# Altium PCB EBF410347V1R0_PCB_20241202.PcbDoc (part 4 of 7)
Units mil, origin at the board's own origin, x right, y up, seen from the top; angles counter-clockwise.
Board outline 5098.43 x 3464.57 mil, 6 copper layers (TOP, GND02, ART03, ART04, PWR05, BOTTOM), stack 47.2 mil thick; 566 components, 452 nets, 1905 pads, 1432 vias.
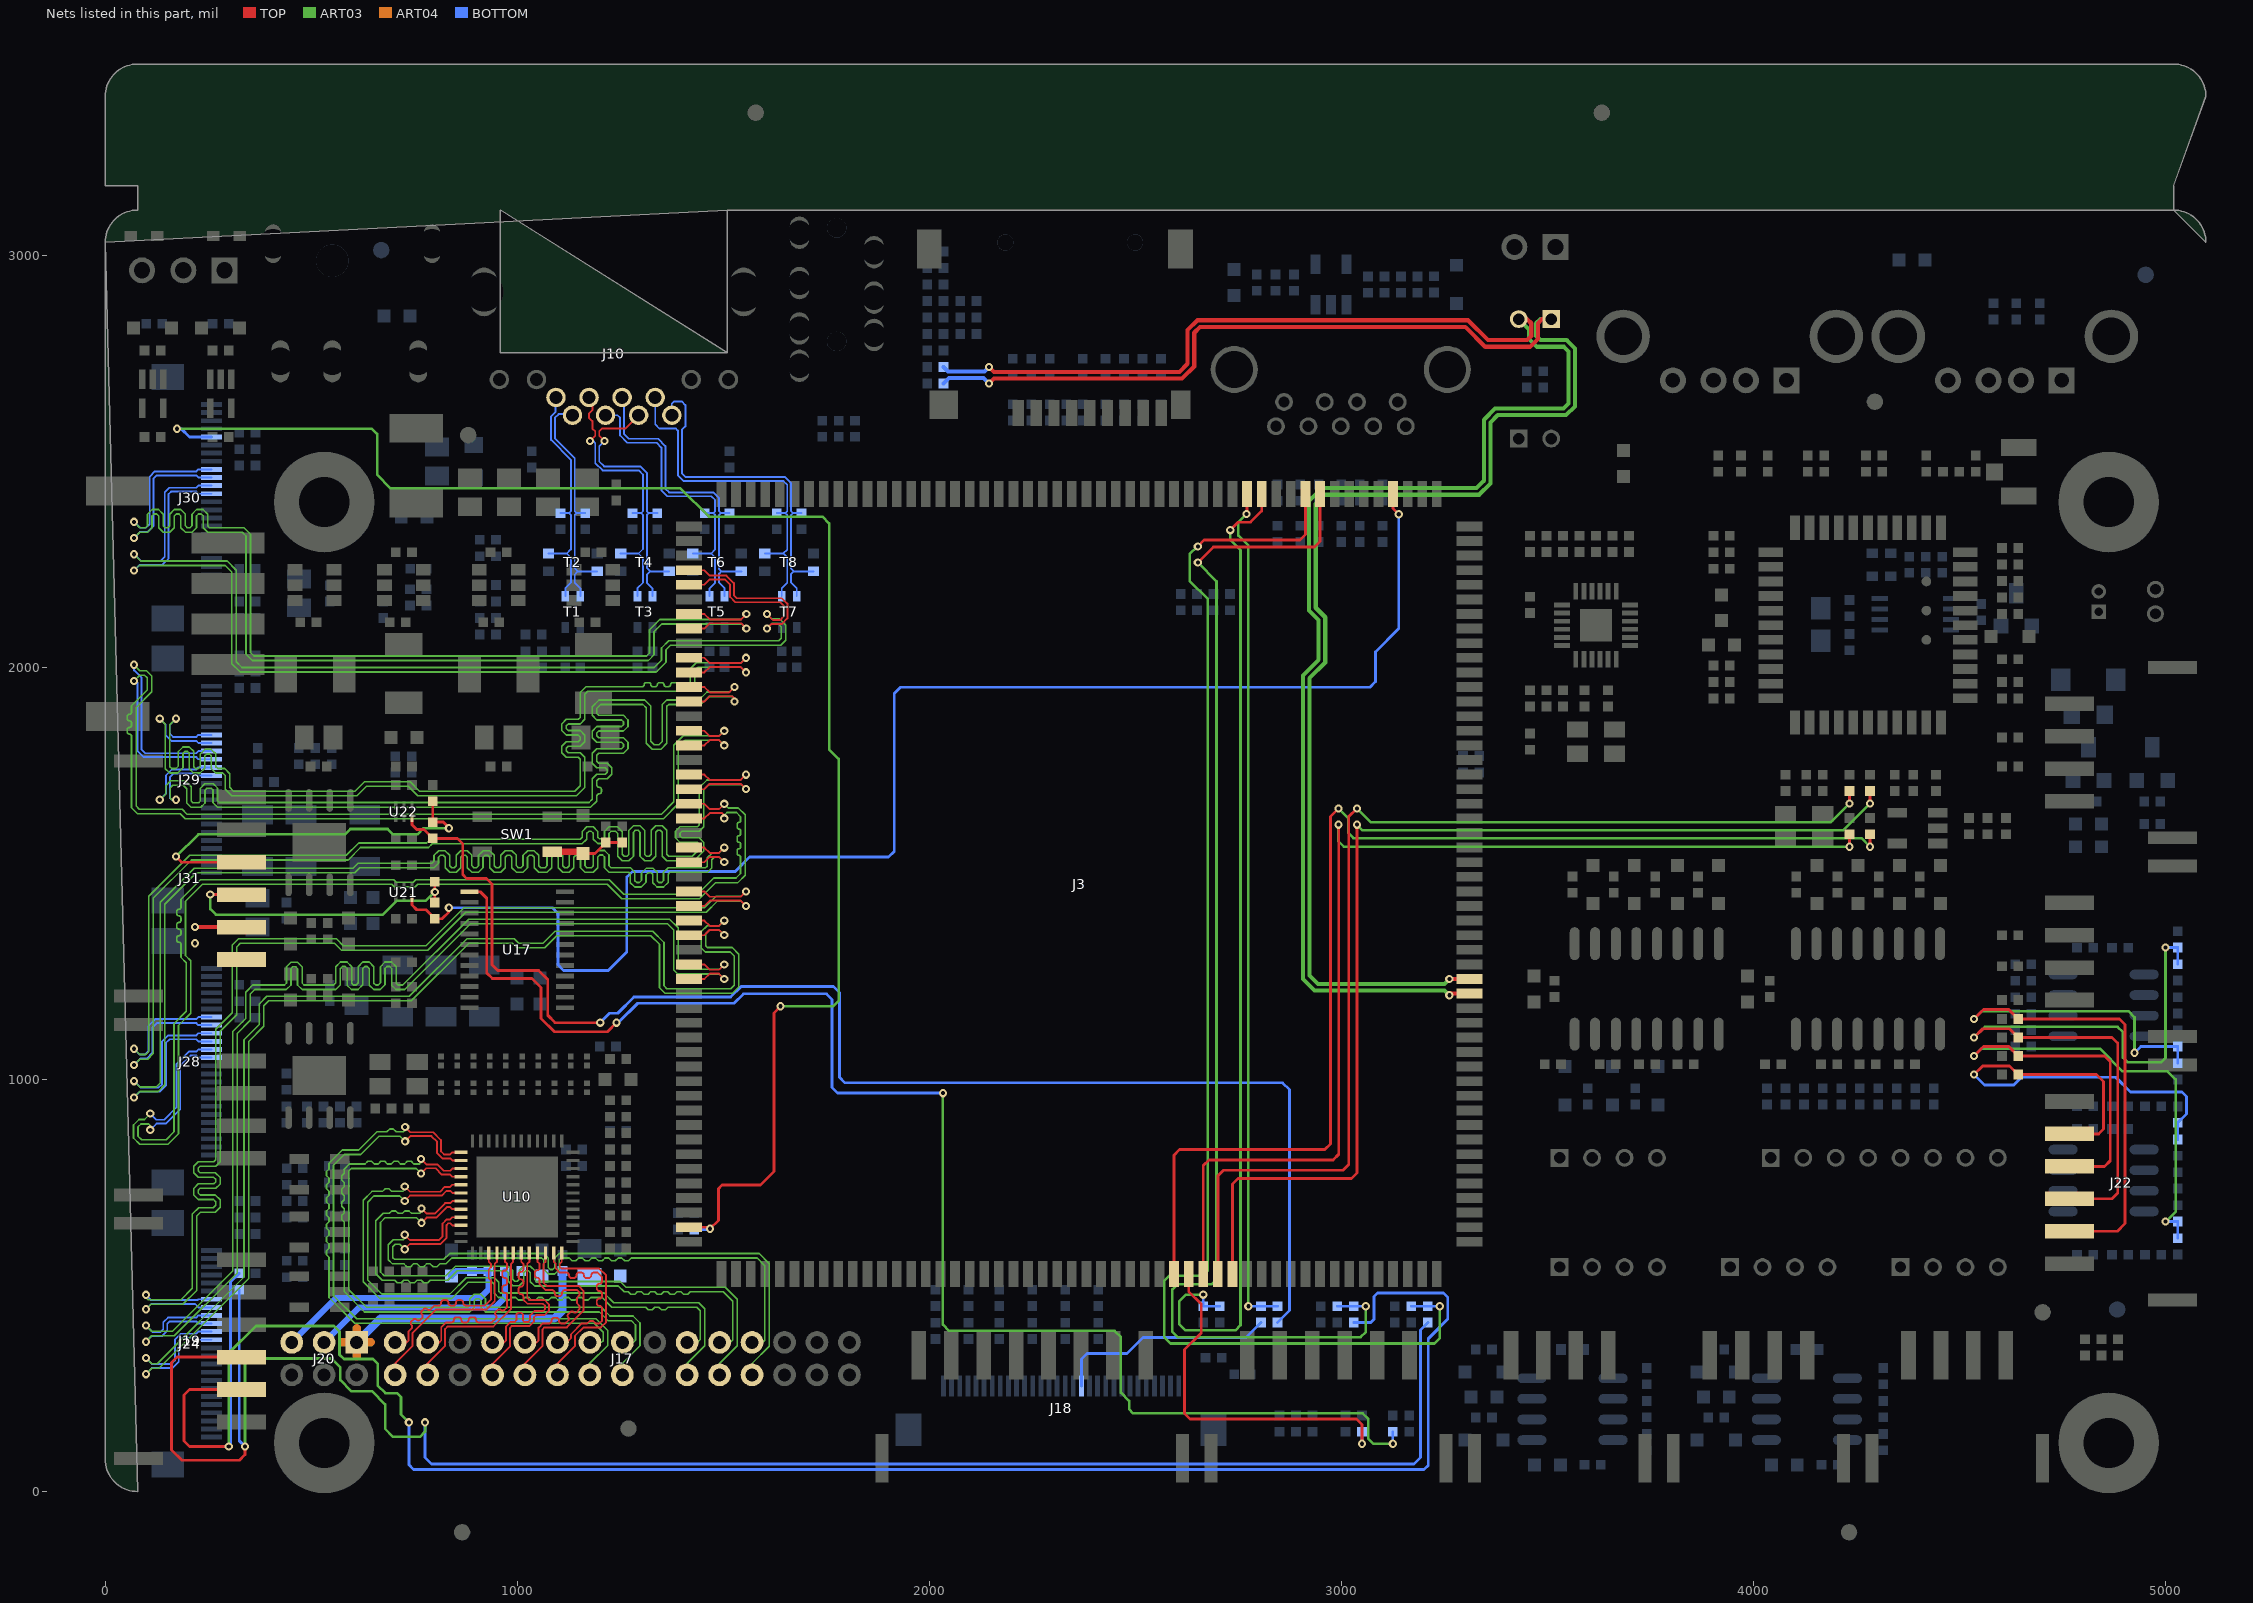
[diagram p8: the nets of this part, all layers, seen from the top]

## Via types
v1: diameter 20, hole 10, TOP to BOTTOM, 1432 vias

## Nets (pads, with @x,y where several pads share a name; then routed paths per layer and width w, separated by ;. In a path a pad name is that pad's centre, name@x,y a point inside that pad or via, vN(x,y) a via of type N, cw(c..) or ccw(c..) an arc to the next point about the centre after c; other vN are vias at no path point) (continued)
I2C5_SDA_M1: J3.149 J30.5 R192.2 | length 3899.3
  TOP w6.8: J3.149@1416.89,641.69 1464.19,641.69 v1(1468.13,637.76) 1468.13,638.13 1488.1,658.1 1488.1,734.99 1497.3,744.2 1590.3,744.2 1622.8,776.7 1622.8,1161.8 v1(1639,1178)
  ART03 w6.3: v1(174.34,2579.29) 647.4,2579.29 660,2566.69 660,2468 693,2435 1396.02,2435 1465.02,2366 1740.4,2366 1757,2349.4 1757,1801 1780,1778 1780,1191 1767,1178 v1(1639,1178)
  BOTTOM w6.8: v1(174.34,2579.29) 184.71,2579.29 204.39,2559.61 J30.5@257.91,2559.61 ; R192.2@1429.68,636 1466.37,636 v1(1468.13,637.76)
I2S2_LRCK_M0: J3.182 R157.2 | length 2881.7
  TOP w6.8: J3.182@2594.05,527.52 2594.05,816.4 2607.66,830 2959.8,830 2973.4,843.6 2973.4,1638.4 v1(2993,1658) ; v1(4283.11,1565) R157.2@4283.11,1595.32
  ART03 w6.3: v1(2993,1658) 3017,1634 3017,1598.6 3029.6,1586 4262.11,1586 v1(4283.11,1565)
I2S2_SCLK_M0: J3.184 R160.2 | length 2720.8
  TOP w6.8: J3.184@2664.92,527.52 2664.92,791.4 2678.52,805 2980.2,805 2993.8,818.6 2993.8,1617.83 v1(2993,1618.63) ; v1(4233.11,1565) R160.2@4233.11,1595.32
  ART03 w6.3: v1(2993,1618.63) 2993,1578 3006,1565 v1(4233.11,1565)
I2S2_SDI_M0: J3.185 R161.2 | length 2699
  TOP w6.8: J3.185@2700.35,527.52 2700.35,766.4 2713.95,780 3004.4,780 3018,793.6 3018,1638 v1(3038,1658) ; v1(4233.11,1670) R161.2@4233.11,1700.32
  ART03 w6.3: v1(3038,1658) 3072,1624 4187.11,1624 v1(4233.11,1670)
I2S2_SDO_M0: J3.186 R159.2 | length 2685.4
  TOP w6.8: J3.186@2735.79,527.52 2735.79,746.4 2749.39,760 3024.4,760 3038,773.6 v1(3038,1618.63) ; v1(4283.11,1670) R159.2@4283.11,1700.32
  ART03 w6.3: v1(3038,1618.63) 3051.63,1605 4218.11,1605 v1(4283.11,1670)
IO0_C0: D74.1 J22.5 R252.2 R254.2 | length 1657.7
  TOP w6.8: v1(4535.63,1147) 4558.63,1170 4619.79,1170 D74.1@4642.79,1147 4888.4,1147 4902,1133.4 4902,650.5 4883.31,631.81 J22.5@4767.41,631.81
  ART03 w6.3: v1(4535.63,1147) 4554.63,1166 4910,1166 4925,1151 v1(4925,1065)
  BOTTOM w6.8: v1(4925,1065) 4940.32,1080.32 R252.2@5030,1080.32 R254.2@5030,1039.68
IO0_C1: D37.1 J22.4 R256.2 R258.2 | length 1748.3
  TOP w6.8: v1(4535.63,1102) 4556.83,1123.2 4621.59,1123.2 D37.1@4642.79,1102 4870.51,1102 4884.11,1088.4 4884.11,724.15 4870.51,710.55 J22.4@4767.41,710.55
  ART03 w6.3: v1(4535.63,1102) 4561.63,1128 4884,1128 4897,1115 4897,1053 4908,1042 4990,1042 5000.32,1052.32 v1(5000.32,1320.32)
  BOTTOM w6.8: v1(5000.32,1320.32) R256.2@5030,1320.32 R258.2@5030,1279.68
IO0_C6: D36.1 J22.3 R238.2 R249.2 | length 1653.7
  TOP w6.8: v1(4535.63,1057) 4558.63,1080 4619.79,1080 D36.1@4642.79,1057 4852.51,1057 4866.11,1043.4 4866.11,802.89 4852.51,789.29 J22.3@4767.41,789.29
  ART03 w6.3: v1(4535.63,1057) 4553.63,1075 4841,1075 4896,1020 5005,1020 5025,1000 5025,679 5001.32,655.32 v1(5000.32,655.32)
  BOTTOM w6.8: v1(5000.32,655.32) R238.2@5030,655.32 R249.2@5030,614.68
IO0_C7: D35.1 J22.2 R250.2 R251.2 | length 1207.4
  TOP w6.8: v1(4535.63,1012) 4556.83,1033.2 4621.59,1033.2 D35.1@4642.79,1012 4833,1012 4850,995 4850,880 4838.03,868.03 J22.2@4767.41,868.03
  BOTTOM w6.8: v1(4535.63,1012) 4560.63,987 4632,987 4650.54,1005.54 4879.46,1005.54 4915,970 5040,970 5051.2,958.8 5051.2,916.52 R250.2@5030,895.32 R251.2@5030,854.68
LCD_BL_PWM: J3.64 R184.1 R185.1 | length 2061
  TOP w6.8: v1(2769.86,2372.65) 2771.22,2374.01 J3.64@2771.22,2421.22
  ART03 w6.3: v1(2769.86,2372.65) 2750,2352.79 2750,2320 2774.37,2295.63 v1(2774.37,449.68)
  BOTTOM w6.8: v1(2774.37,449.68) R184.1@2805,449.68 R185.1@2845,449.68
LCD_CPT_INT: J3.60 R81.1 R178.1 | length 3235.4
  TOP w6.8: v1(2651.75,2293.91) 2667.01,2309.17 2899.35,2309.17 2912.95,2322.77 J3.60@2912.95,2421.22
  ART03 w6.3: v1(2651.75,2293.91) 2650.91,2293.91 2632,2275 2632,2210 2676,2166 2676,536.6 2663.4,524 2582.6,524 2570,511.4 2570,375.05 2585.6,359.45 3226.14,359.45 3238.74,372.05 v1(3238.74,449.68)
  BOTTOM w6.8: R81.1@3170,449.68 R178.1@3210,449.68 v1(3238.74,449.68)
LCD_CPT_RST: J3.59 R182.1 R183.1 | length 3022.5
  TOP w6.8: v1(2651.75,2254.54) 2689.38,2292.17 2934.79,2292.17 2948.39,2305.77 J3.59@2948.39,2421.22
  ART03 w6.3: v1(2651.75,2254.54) 2697,2209.28 2697,515.6 2684.4,503 2602.6,503 2590,490.4 2590,387.6 2602.6,375 3046.77,375 3059.37,387.6 v1(3059.37,449.67)
  BOTTOM w6.8: R182.1@2990,449.68 R183.1@3030,449.68 v1(3059.37,449.67)
LCD_RST: J3.63 R186.1 R187.1 | length 2425.2
  TOP w6.8: v1(2730.49,2333.28) 2749.89,2352.68 2779.57,2352.68 2806.65,2379.76 J3.63@2806.65,2421.22
  ART03 w6.3: v1(2665,478) 2623,478 2607,462 2607,406 2621.84,391.16 2742.62,391.16 2755.22,403.76 2755.22,2284.78 2730.49,2309.51 v1(2730.49,2333.28)
  BOTTOM w6.8: v1(2665,478) R186.1@2665,449.68 R187.1@2705,449.68
LED_BLUE: J3.183 R103.1 | length 884.7
  TOP w6.8: J3.183@2629.49,527.52 2629.49,485.51 2660,455 2660,385 2619.6,344.6 2619.6,189.6 2633.2,176 3036.4,176 3050,162.4 v1(3050,116)
  BOTTOM w6.8: v1(3050,116) R103.1@3050,145.32
LED_RED: R98.1 U17.13 | length 3625.4
  TOP w6.8: U17.13@883.86,1455.75 910.25,1455.75 926,1440 926,1258.6 939.6,1245 1036,1245 1058,1223 1058,1148 1090,1116 1218.74,1116 v1(1240.74,1138)
  ART03 w6.3: v1(2033,967) 2033,405 2048,390 2450,390 2465,375 2465,240 2485,220 2485,200 2495,190 3052,190 3065,177 3065,128.6 3077.6,116 v1(3125,116)
  BOTTOM w6.8: v1(1240.74,1138) 1245.1,1138 1292.36,1185.25 1526.25,1185.25 1549,1208 1750.4,1208 1764,1194.4 1764,980.6 1777.6,967 v1(2033,967) ; v1(3125,116) R98.1@3125,145.32
LVDS_3V3: C96.1 C97.1 J20.5 R78.2 | length 670.4
  BOTTOM w15: J20.5@452.76,362.2 560.55,470 910,470 930,490 C96.1@930,535.32 C97.1@890,535.32 851.82,535.32 R78.2@840,523.5
LVDS_5V: C104.1 C105.1 J20.3 R84.2 | length 548.5
  BOTTOM w15: J20.3@531.5,362.2 616.29,447 947,447 970,470 C104.1@970,535.32
LVDS_12V: C98.1 C99.1 J20.1 J31.1 J31.2 R79.2 | length 878.3
  TOP w10: v1(218,1370.08) J31.2@330.71,1370.08
  ART04 w20: 575.67,362.2 J20.1@610.24,362.2 ; 610.24,327.64 J20.1@610.24,362.2 ; 610.24,396.77 J20.1@610.24,362.2 ; 644.8,362.2 J20.1@610.24,362.2
  BOTTOM w20: J20.1@610.24,362.2 668.03,420 1090,420 1110,440 C98.1@1110,535.32
  other v1: 218,1330.71
LVDS_BL_EN: J3.54 R213.1 U21.3 | length 3627.6
  TOP w6.8: U21.3@744.68,1440.24 744.68,1423.32 756,1412 778.32,1412 R213.1@800,1390.32 817.32,1390.32 834,1407 v1(834,1417) ; J3.54@3125.55,2421.22 3125.55,2385.82 v1(3139.37,2372)
  BOTTOM w6.8: v1(834,1417) 1085.4,1417 1099,1403.4 1099,1278.6 1112.6,1265 1221,1265 1266,1310 1266,1491.4 1279.6,1505 1529,1505 1564,1540 1901.4,1540 1915,1553.6 1915,1937 1930,1952 3069.4,1952 3083,1965.6 3083,2038 3139.37,2094.37 v1(3139.37,2372)
LVDS_BL_PWM: R185.2 R214.1 U22.3 | length 3392.4
  TOP w6.8: U22.3@744.68,1635.24 744.68,1618.32 756,1607 773.32,1607 R214.1@795,1585.32 854.68,1585.32 868,1572 868,1497 877,1488 925.4,1488 939,1474.4 939,1278.6 952.6,1265 1052,1265 1074,1243 1074,1156 1092,1138 v1(1201.37,1138)
  BOTTOM w6.8: v1(1201.37,1138) 1224.37,1161 1244,1161 1283,1200 1518,1200 1543.8,1225.8 1767.43,1225.8 1782,1211.23 1782,1005.6 1795.6,992 2857.4,992 2874,975.4 2874,439.32 R185.2@2845,410.32
LVDS_BLEN: J31.3 R213.2 R215.2 | length 734.7
  TOP w6.8: v1(255,1448.82) J31.3@330.71,1448.82 ; R213.2@800,1429.68 v1(800,1455) R215.2@800,1480.32
  ART03 w6.3: v1(255,1448.82) 255,1414 269,1400 674,1400 708,1434 778,1434 799,1455 v1(800,1455)
LVDS_BLPWM: J31.4 R214.2 R216.2 | length 962.3
  TOP w6.8: v1(171.82,1541.17) 185.43,1527.56 J31.4@330.71,1527.56 ; R216.2@795,1675.32 R214.2@795,1624.68 820.4,1624.68 834,1611.08 v1(834,1610)
  ART03 w6.3: v1(171.82,1541.17) 225.87,1595.22 582.3,1595.22 595.08,1608 685.63,1608 698.63,1595 758,1595 773,1610 v1(834,1610)
LVDS_CPT_INT: J19.3 R80.2 R178.2 | length 4638.9
  TOP w6.8: J19.3@330.71,326.46 174.6,326.46 161,312.86 161,101 186,76 325.77,76 339.37,89.6 v1(339.37,109.42)
  ART03 w6.3: v1(339.37,109.42) 339.37,310.4 351.97,323 549,323 570.5,301.5 570.5,270.5 597,244 647,244 679.5,211.5 679.5,152.5 699,133 764,133 776.37,145.37 v1(776.37,168)
  BOTTOM w6.8: R80.2@325.32,490 325.32,123.48 v1(339.37,109.42) ; v1(776.37,168) 776.37,82.8 792.17,67 3176,67 3192,83 3192,392.32 R178.2@3210,410.32
LVDS_CPT_RST: J19.2 R82.2 R183.2 | length 4986.6
  TOP w6.8: v1(300,109.42) 204.57,109.42 191,123 191,234.12 204.6,247.72 J19.2@330.71,247.72
  ART03 w6.3: 650,321.6 661,310.6 661,258 680,239 708.4,239 718,229.4 718,187 v1(737,168)
  ART03 w6.8: v1(300,109.42) 300,336 366,402 555.4,402 569,388.4 569,332 579.4,321.6 650,321.6
  BOTTOM w6.8: v1(300,109.42) 300,110 304.12,114.12 304.12,508.8 R82.2@325.32,530 ; v1(737,168) 737,65 748.5,53.5 3200.81,53.5 3211,63.69 3211,371 3258.14,418.14 3258.14,471.86 3248,482 3088,482 3079.34,473.34 3079.34,418.34 3071.31,410.31 3059.37,410.31 R183.2@3030,410.32
LVDS_TXA_CLKN: J17.15 U10.27 | length 1508.3
  TOP w4.5: v1(766.69,807.04) 779.48,794.25 805.75,794.25 821.2,778.8 837.3,778.8 842.39,783.9 U10.27@864.08,783.9
  ART03 w4: v1(766.69,807.04) 766.69,799 762.69,795 748.85,795 742.45,801.4 732.85,801.4 726.45,795 716.85,795 710.45,801.4 700.85,801.4 694.45,795 684.85,795 678.45,801.4 668.85,801.4 662.45,795 652.85,795 646.45,801.4 636.85,801.4 630.45,795 592.44,795 580,782.56 580,772.33 574,766.33 574,756.33 580,750.33 580,740.33 574,734.33 574,724.33 580,718.33 580,708.33 574,702.33 574,692.33 580,686.33 580,676.33 574,670.33 574,660.33 580,654.33 580,485.44 629.44,436 884.75,436 895.88,447.13 895.88,463.31 900.57,468 907.2,468 911.88,463.31 911.88,447.13 923.01,436 1199.44,436 1220.44,415 1276.44,415 1287,404.44 1287,367.2 1282,362.2 J17.15@1255,362.2
LVDS_TXA_CLKP: J17.16 U10.28 | length 1511.7
  TOP w4.5: v1(766.69,771.96) 779.48,784.75 801.81,784.75 817.26,769.3 837.3,769.3 842.39,764.21 U10.28@864.08,764.21
  ART03 w4: v1(766.69,771.96) 754.64,784 597,784 591,778 591,490 634,447 880.2,447 884.88,451.69 884.88,467.87 896.01,479 911.75,479 922.88,467.87 922.88,451.69 927.57,447 1204,447 1225,426 1281,426 1298,409 1298,354 1255,311 J17.16@1255,283.46
LVDS_TXA_D0N: J17.7 U10.33 | length 1525.5
  TOP w4.5: v1(727,623.29) 739.79,610.5 810,610.5 819,619.5 819,650.63 829.06,660.69 837.3,660.69 842.39,665.79 U10.33@864.08,665.79
  ART03 w4: v1(727,623.29) 727,615.25 723,611.25 699.25,611.25 687,599 687,563 697.45,552.55 725.25,552.55 731.8,546 741.25,546 747.8,552.55 757.25,552.55 763.8,546 773.25,546 779.8,552.55 789.25,552.55 795.8,546 805.25,546 811.8,552.55 826.55,552.55 841,567 1059.53,567 1064.22,562.31 1064.22,539.13 1075.35,528 1091.09,528 1102.22,539.13 1102.22,562.31 1106.9,567 1126,567 1133,560 1142,560 1149,567 1158,567 1165,560 1174,560 1181,567 1190,567 1197,560 1206,560 1213,567 1222,567 1229,560 1238,560 1245,567 1254,567 1261,560 1270,560 1277,567 1582.44,567 1601,548.44 1601,367 1596.2,362.2 J17.7@1569.96,362.2
LVDS_TXA_D0P: J17.8 U10.34 | length 1525.2
  TOP w4.5: v1(727,588.21) 739.79,601 813.94,601 828.5,615.56 828.5,646.69 833,651.19 837.3,651.19 842.39,646.1 U10.34@864.08,646.1
  ART03 w4: v1(727,588.21) 714.96,600.25 703.81,600.25 698,594.44 698,567.56 702,563.55 822,563.55 836.44,578 1064.09,578 1075.22,566.87 1075.22,543.69 1079.9,539 1086.53,539 1091.22,543.69 1091.22,566.87 1102.35,578 1587,578 1612,553 1612,353 1569.96,310.96 J17.8@1569.96,283.46
LVDS_TXA_D1N: J17.9 U10.31 | length 1528.3
  TOP w4.5: v1(767.37,687.29) 780.16,674.5 799.5,674.5 825.06,700.06 837.3,700.06 842.39,705.16 U10.31@864.08,705.16
  ART03 w4: v1(767.37,687.29) 767.37,679.37 763.25,675.25 743.26,675.25 737.51,681 727.26,681 721.51,675.25 711.26,675.25 705.51,681 695.26,681 689.51,675.25 674.69,675.25 657,657.56 657,528.44 672.44,513 702.85,513 708.85,507 718.85,507 724.85,513 734.85,513 740.85,507 750.85,507 756.85,513 766.85,513 772.85,507 782.85,507 788.85,513 831.56,513 854.56,536 973.24,536 977.93,531.31 977.93,510.73 989.06,499.6 1004.8,499.6 1015.93,510.73 1015.93,531.31 1020.62,536 1027.24,536 1031.93,531.31 1031.93,509.44 1042.37,499 1245.44,499 1259.44,485 1269.6,485 1275.6,479 1285.6,479 1291.6,485 1301.6,485 1307.6,479 1317.6,479 1323.6,485 1333.6,485 1339.6,479 1349.6,479 1355.6,485 1365.6,485 1371.6,479 1381.6,479 1387.6,485 1397.6,485 1403.6,479 1413.6,479 1419.6,485 1500,485 1523,462 1523,368 1517.2,362.2 J17.9@1491.22,362.2
LVDS_TXA_D1P: J17.10 U10.32 | length 1524.2
  TOP w4.5: v1(767.37,652.21) 780.16,665 803.44,665 829,690.56 837.3,690.56 842.39,685.47 U10.32@864.08,685.47
  ART03 w4: v1(767.37,652.21) 755.33,664.25 679.25,664.25 668,653 668,533 677,524 827,524 850,547 977.8,547 988.93,535.87 988.93,515.29 993.62,510.6 1000.24,510.6 1004.93,515.29 1004.93,535.87 1016.06,547 1031.8,547 1042.93,535.87 1042.93,514 1046.93,510 1250,510 1264,496 1504.56,496 1534,466.56 1534,354 1491.22,311.22 J17.10@1491.22,283.46
LVDS_TXA_D2N: J17.11 U10.29 | length 1514
  TOP w4.5: v1(727,740.54) 739.79,727.75 812.75,727.75 824.43,739.43 837.3,739.43 842.39,744.53 U10.29@864.08,744.53
  ART03 w4: v1(727,740.54) 727,733 722.5,728.5 695.5,728.5 689,735 679.5,735 673,728.5 647.5,728.5 626,707 626,509 666.4,468.6 841.16,468.6 880.56,508 939.48,508 944.17,503.31 944.17,481.44 954.61,471 964.71,471 970.71,465 980.71,465 986.71,471 996.71,471 1002.71,465 1012.71,465 1018.71,471 1028.71,471 1034.71,465 1044.71,465 1050.71,471 1060.71,471 1066.71,465 1076.71,465 1082.71,471 1092.71,471 1098.71,465 1108.71,465 1114.71,471 1124.71,471 1130.71,465 1140.71,465 1146.71,471 1156.71,471 1162.71,465 1172.71,465 1178.71,471 1206,471 1229.73,447.27 1311.78,447.27 1318.05,441 1327.78,441 1334.05,447.27 1343.78,447.27 1350.05,441 1359.78,441 1366.05,447.27 1435.73,447.27 1444,439 1444,369 1437.2,362.2 J17.11@1412.48,362.2
LVDS_TXA_D2P: J17.12 U10.30 | length 1509.6
  TOP w4.5: v1(727,705.46) 739.79,718.25 816.69,718.25 828.37,729.93 837.3,729.93 842.39,724.84 U10.30@864.08,724.84
  ART03 w4: v1(727,705.46) 714.96,717.5 652.06,717.5 637,702.44 637,513.56 670.96,479.6 836.6,479.6 876,519 944.04,519 955.17,507.87 955.17,486 959.17,482 1210.56,482 1234.29,458.27 1440.29,458.27 1455,443.56 1455,354 1412.48,311.48 J17.12@1412.48,283.46
LVDS_TXA_D3N: J17.17 U10.25 | length 1529.2
  TOP w4.5: v1(728,885.04) 740.79,872.25 795.75,872.25 815,853 815,825.43 822.26,818.17 837.3,818.17 842.39,823.27 U10.25@864.08,823.27
  ART03 w4: v1(728,885.04) 728,877 724,873 706.35,873 699.35,880 690.35,880 683.35,873 659.44,873 615.44,829 575.44,829 543,796.56 543,782.87 537,776.87 537,766.87 543,760.87 543,750.87 537,744.87 537,734.87 543,728.87 543,718.87 537,712.87 537,702.87 543,696.87 543,686.87 537,680.87 537,670.87 543,664.87 543,654.87 537,648.87 537,638.87 543,632.87 543,622.87 537,616.87 537,606.87 543,600.87 543,590.87 537,584.87 537,574.87 543,568.87 543,471 605.6,408.4 1186.6,408.4 1208.44,386.56 1208.44,366.2 1204.44,362.2 J17.17@1176.26,362.2
LVDS_TXA_D3P: J17.18 U10.26 | length 1532.4
  TOP w4.5: v1(728,849.96) 740.79,862.75 791.82,862.75 805.5,849.07 805.5,821.5 818.32,808.67 837.3,808.67 842.39,803.58 U10.26@864.08,803.58
  ART03 w4: v1(728,849.96) 715.96,862 664,862 620,818 580,818 554,792 554,475.56 610.16,419.4 1191.16,419.4 1219.44,391.12 1219.44,354.44 1176.26,311.26 J17.18@1176.26,283.46
LVDS_TXB_CLKN: J17.27 U10.41 | length 449
  TOP w4.5: J17.27@782.56,362.2 811,362.2 815.5,366.7 815.5,398.5 827.5,410.5 839.88,410.5 ccw(c839.88,416.75) 846.13,416.75 cw(c852.38,416.75) 852.38,423 857.88,423 cw(c857.88,416.75) 864.13,416.75 ccw(c870.38,416.75) 870.38,410.5 875.88,410.5 ccw(c875.88,416.75) 882.13,416.75 cw(c888.38,416.75) 888.38,423 893.88,423 cw(c893.88,416.75) 900.13,416.75 ccw(c906.38,416.75) 906.38,410.5 938.5,410.5 948.02,420.02 ccw(c944.02,424.02) 948.02,428.02 cw(c952.02,432.02) 948.02,436.02 952.75,440.75 cw(c956.75,436.75) 960.75,440.75 ccw(c964.75,444.75) 968.75,440.75 975.47,447.47 975.47,476.81 ccw(c969.58,476.81) 969.58,482.7 cw(c969.58,488.58) 963.7,488.58 963.7,494.81 cw(c969.58,494.81) 969.58,500.7 ccw(c969.58,506.58) 975.47,506.58 975.47,512.81 ccw(c969.58,512.81) 969.58,518.7 cw(c969.58,524.58) 963.7,524.58 963.7,530.81 cw(c969.58,530.81) 969.58,536.7 ccw(c969.58,542.58) 975.47,542.58 975.47,552.4 970.37,557.49 U10.41@970.37,579.17
LVDS_TXB_CLKP: J17.28 U10.42 | length 446.7
  TOP w4.5: J17.28@782.56,283.46 782.56,311.56 825,354 825,394.56 831.44,401 942.44,401 984.97,443.53 984.97,552.4 990.06,557.49 U10.42@990.06,579.17
LVDS_TXB_D0N: J17.19 U10.47 | length 467.8
  TOP w4.5: U10.47@1088.48,579.17 1088.48,557.49 1093.58,552.4 1093.58,541.56 1103.64,531.5 1119.34,531.5 cw(c1119.34,525.25) 1125.59,525.25 ccw(c1132.84,525.25) 1132.84,518 1136.34,518 ccw(c1136.34,525.25) 1143.59,525.25 cw(c1149.84,525.25) 1149.84,531.5 1155.34,531.5 cw(c1155.34,525.25) 1161.59,525.25 ccw(c1168.84,525.25) 1168.84,518 1172.34,518 ccw(c1172.34,525.25) 1179.59,525.25 cw(c1185.84,525.25) 1185.84,531.5 1195.06,531.5 1206,520.56 1206,511.06 cw(c1199.5,511.06) 1199.5,504.56 ccw(c1199.5,498.06) 1193,498.06 1193,493.06 ccw(c1199.5,493.06) 1199.5,486.56 cw(c1199.5,480.06) 1206,480.06 1206,475.06 cw(c1199.5,475.06) 1199.5,468.56 ccw(c1199.5,462.06) 1193,462.06 1193,457.06 ccw(c1199.5,457.06) 1199.5,450.56 cw(c1199.5,444.06) 1206,444.06 1206,415 1199,408 1190,408 1184,414 1176,414 1170,408 1157,408 1130.5,381.5 1130.5,372 1120.7,362.2 J17.19@1097.52,362.2
LVDS_TXB_D0P: J17.20 U10.48 | length 471.4
  TOP w4.5: J17.20@1097.52,283.46 1097.52,310.52 1140,353 1140,377.56 1160.93,398.5 1202.94,398.5 1215.5,411.06 1215.5,524.5 1199,541 1107.58,541 1103.08,545.5 1103.08,552.4 1108.17,557.49 U10.48@1108.17,579.17
LVDS_TXB_D1N: J17.21 U10.45 | length 472.1
  TOP w4.5: J17.21@1018.78,362.2 1047,362.2 1052,367.2 1052,397.94 1062.06,408 1076.37,408 ccw(c1076.37,415) 1083.37,415 cw(c1090.37,415) 1090.37,422 1094.37,422 cw(c1094.37,415) 1101.37,415 ccw(c1108.37,415) 1108.37,408 1116.56,408 1123.77,415.21 ccw(c1119.88,419.1) 1123.77,422.99 cw(c1127.66,426.88) 1123.77,430.77 1128.72,435.72 cw(c1132.61,431.83) 1136.5,435.72 ccw(c1140.39,439.61) 1144.28,435.72 1151,442.44 1151,451 1145,457 1145,470 1151,476 1151,483.56 1145.06,489.5 1116.65,489.5 ccw(c1116.65,481.75) 1108.9,481.75 cw(c1101.15,481.75) 1101.15,474 1098.65,474 cw(c1098.65,481.75) 1090.9,481.75 ccw(c1083.15,481.75) 1083.15,489.5 1068.06,489.5 1054.21,503.36 1054.21,513.13 ccw(c1048.32,513.13) 1048.32,519.01 cw(c1048.32,524.9) 1042.44,524.9 1042.44,531.13 cw(c1048.32,531.13) 1048.32,537.01 ccw(c1048.32,542.9) 1054.21,542.9 1054.21,552.4 1049.12,557.49 U10.45@1049.12,579.17
LVDS_TXB_D1P: J17.22 U10.46 | length 473.6
  TOP w4.5: J17.22@1018.78,283.46 1018.78,310.78 1061.5,353.5 1061.5,394 1066,398.5 1120.5,398.5 1160.5,438.5 1160.5,487.5 1149,499 1072,499 1063.71,507.29 1063.71,552.4 1068.8,557.49 U10.46@1068.8,579.17
LVDS_TXB_D2N: J17.23 U10.43 | length 431.7
  TOP w4.5: J17.23@940.04,362.2 968,362.2 973,367.21 973,401.44 983.06,411.5 993.5,411.5 998,416 998,430 1002,434 1010,434 1014,430 1014,415 1017.5,411.5 1026.34,411.5 1030.84,416 1030.84,426.84 1041.89,437.89 1062.23,437.89 1067.5,443.16 1067.5,450.62 1062.23,455.89 1024.9,455.89 1014.84,465.95 1014.84,473.41 ccw(c1008.95,473.41) 1008.95,479.29 cw(c1008.95,485.18) 1003.07,485.18 1003.07,491.41 cw(c1008.95,491.41) 1008.95,497.29 ccw(c1008.95,503.18) 1014.84,503.18 1014.84,509.41 ccw(c1008.95,509.41) 1008.95,515.29 cw(c1008.95,521.18) 1003.07,521.18 1003.07,527.41 cw(c1008.95,527.41) 1008.95,533.29 ccw(c1008.95,539.18) 1014.84,539.18 1014.84,552.4 1009.75,557.49 U10.43@1009.75,579.17
LVDS_TXB_D2P: J17.24 U10.44 | length 435.5
  TOP w4.5: J17.24@940.04,283.46 940.04,310.04 982.5,352.5 982.5,397.5 987,402 1030.27,402 1040.34,412.06 1040.34,422.9 1045.83,428.39 1066.16,428.39 1077,439.23 1077,454.56 1066.16,465.39 1028.84,465.39 1024.34,469.89 1024.34,552.4 1029.43,557.49 U10.44@1029.43,579.17
LVDS_TXB_D3N: J17.29 U10.39 | length 468.1
  TOP w4.5: J17.29@703.82,362.2 732,362.2 736.5,366.71 736.5,388.94 743.22,395.66 ccw(c738.83,400.05) 743.22,404.44 cw(c747.61,408.83) 743.22,413.22 747.17,417.17 cw(c751.56,412.78) 755.95,417.17 ccw(c760.34,421.56) 764.73,417.17 768.68,421.11 ccw(c764.28,425.5) 768.68,429.89 cw(c773.07,434.29) 768.68,438.68 772.62,442.62 cw(c777.01,438.23) 781.4,442.62 ccw(c785.79,447.01) 790.19,442.62 798.56,451 808.06,451 ccw(c808.06,458) 815.06,458 cw(c822.06,458) 822.06,465 826.06,465 cw(c826.06,458) 833.06,458 ccw(c840.06,458) 840.06,451 844.06,451 ccw(c844.06,458) 851.06,458 cw(c858.06,458) 858.06,465 862.06,465 cw(c862.06,458) 869.06,458 ccw(c876.06,458) 876.06,451 921,451 936.1,466.1 936.1,513 931,518.1 931,539 936,544 936.1,544 936.1,552.4 931,557.49 U10.39@931,579.17
LVDS_TXB_D3P: J17.30 U10.40 | length 469.7
  TOP w4.5: J17.30@703.82,283.46 703.82,311.56 746,353.74 746,385 802.5,441.5 924.94,441.5 945.6,462.16 945.6,552.4 950.69,557.49 U10.40@950.69,579.17
MASKROM: C165.1 D76.1 R261.2 SW1.1 | length 183
  TOP w6.8: D76.1@1160,1548.74 1188.42,1548.74 C165.1@1215,1575.32 R261.2@1255,1575.32
  TOP w15: SW1.1@1084.65,1552.68 1156.06,1552.68 D76.1@1160,1548.74
MDIN0_RJ45: D10.2 J10.2 T1.2 T2.2 | length 583.7
  BOTTOM w4.5: J10.2@1134.13,2612.2 1131.33,2615 1100.5,2615 1091.5,2606 1091.5,2556.19 1139.75,2507.94 1139.75,2379.18 1144.25,2374.68 ; T1.2@1153.21,2172.89 1153.21,2192.11 1139.75,2205.57 1139.75,2225.75 1147.35,2233.35 ; D10.2@1165,2374.68 1144.25,2374.68 ; T2.2@1194.06,2233.35 1147.35,2233.35 ; 1144.25,2374.68 1139.75,2370.18 1139.75,2240.94 1147.35,2233.35
MDIN1_RJ45: D12.2 J10.6 T3.2 T4.2 | length 705.1
  TOP w4.5: v1(1211.79,2550) 1199,2562.79 1199,2573 1206.33,2580.33 1262.89,2580.33 J10.6@1294.76,2612.2
  BOTTOM w4.5: v1(1211.79,2550) 1199,2537.21 1199,2500 1211,2488 1299,2488 1314.75,2472.25 1314.75,2379.18 1319.25,2374.68 ; T3.2@1328.21,2172.89 1328.21,2192.11 1314.75,2205.57 1314.75,2225 1323.1,2233.35 ; D12.2@1340,2374.68 1319.25,2374.68 ; T4.2@1369.06,2233.35 1323.1,2233.35 ; 1319.25,2374.68 1314.75,2370.18 1314.75,2241.69 1323.1,2233.35
MDIN2_RJ45: D14.2 J10.5 T5.2 T6.2 | length 767.5
  BOTTOM w4.5: J10.5@1254.6,2655.51 1259,2651.11 1259,2567 1271,2555 1342,2555 1359.5,2537.5 1359.5,2434 1368.5,2425 1475.19,2425 1489.75,2410.44 1489.75,2379.18 1494.25,2374.68 ; T5.2@1503.21,2172.89 1503.21,2192.11 1489.75,2205.57 1489.75,2228 1495.1,2233.35 ; D14.2@1515,2374.68 1494.25,2374.68 ; T6.2@1544.06,2233.35 1495.1,2233.35 ; 1494.25,2374.68 1489.75,2370.18 1489.75,2238.69 1495.1,2233.35
MDIN3_RJ45: D16.2 J10.8 T7.2 T8.2 | length 869.4
  BOTTOM w4.5: J10.8@1375.07,2612.2 1375,2612.28 1375,2640 1381,2646 1399,2646 1408,2637 1408,2585 1399.5,2576.5 1399.5,2471 1408.5,2462 1650.19,2462 1664.75,2447.44 1664.75,2379.18 1669.25,2374.68 ; T7.2@1678.21,2172.89 1678.21,2192.11 1664.75,2205.57 1664.75,2227 1671.1,2233.35 ; D16.2@1690,2374.68 1669.25,2374.68 ; T8.2@1719.06,2233.35 1671.1,2233.35 ; 1669.25,2374.68 1664.75,2370.18 1664.75,2239.69 1671.1,2233.35
MDIP0_RJ45: D9.2 J10.1 T1.3 T2.4 | length 590.2
  BOTTOM w4.5: T2.4@1075.94,2276.65 1120.35,2276.65 ; J10.1@1093.97,2655.51 1093,2654.54 1093,2620.94 1082,2609.94 1082,2552.25 1130.25,2504 1130.25,2379.18 1125.75,2374.68 ; D9.2@1105,2374.68 1125.75,2374.68 ; T1.3@1116.79,2172.89 1116.79,2192.11 1130.25,2205.57 1130.25,2266.75 1120.35,2276.65 ; 1120.35,2276.65 1130.25,2286.56 1130.25,2370.18 1125.75,2374.68
MDIP1_RJ45: D11.2 J10.3 T3.3 T4.4 | length 692.9
  TOP w4.5: J10.3@1174.29,2655.51 1182.57,2647.23 1182.57,2624.61 1174,2616.03 1174,2606.61 1182.57,2598.03 1182.57,2579.93 1189.5,2573 1189.5,2562.79 v1(1176.71,2550)
  BOTTOM w4.5: v1(1176.71,2550) 1184,2550 1189.5,2544.5 1189.5,2496.06 1207.06,2478.5 1295.06,2478.5 1305.25,2468.31 1305.25,2379.18 1300.75,2374.68 ; T4.4@1250.94,2276.65 1294.35,2276.65 ; D11.2@1280,2374.68 1300.75,2374.68 ; T3.3@1291.79,2172.89 1291.79,2192.11 1305.25,2205.57 1305.25,2265.75 1294.35,2276.65 ; 1294.35,2276.65 1305.25,2287.56 1305.25,2370.18 1300.75,2374.68
MDIP2_RJ45: D13.2 J10.4 T5.3 T6.4 | length 753.1
  BOTTOM w4.5: J10.4@1214.44,2612.2 1243.3,2612.2 1249.5,2606 1249.5,2563.06 1267.06,2545.5 1338.06,2545.5 1350,2533.56 1350,2430.06 1364.56,2415.5 1471.25,2415.5 1480.25,2406.5 1480.25,2379.18 1475.75,2374.68 ; T6.4@1425.94,2276.65 1470.35,2276.65 ; D13.2@1455,2374.68 1475.75,2374.68 ; T5.3@1466.79,2172.89 1466.79,2192.11 1480.25,2205.57 1480.25,2266.75 1470.35,2276.65 ; 1470.35,2276.65 1480.25,2286.56 1480.25,2370.18 1475.75,2374.68
MDIP3_RJ45: D15.2 J10.7 T7.3 T8.4 | length 863.2
  BOTTOM w4.5: J10.7@1334.92,2655.51 1335,2655.43 1335,2590 1345,2580 1385,2580 1390,2575 1390,2467.06 1404.56,2452.5 1646.25,2452.5 1655.25,2443.5 1655.25,2379.18 1650.75,2374.68 ; T8.4@1600.94,2276.65 1601.29,2277 1646,2277 ; D15.2@1630,2374.68 1650.75,2374.68 ; T7.3@1641.79,2172.89 1641.79,2192.11 1655.25,2205.57 1655.25,2267.75 1646,2277 ; 1646,2277 1655.25,2286.25 1655.25,2370.18 1650.75,2374.68
MIC1_INN: J3.19 J4.1 R27.2 | length 4363.9
  TOP w10: v1(2145,2689.37) 2156.8,2701.17 2613.63,2701.17 2643,2730.55 2643,2743.79 2643,2812.37 2657.37,2826.74 3300.87,2826.74 3349.25,2778.37 3458,2778.37 3477,2797.37 3477,2835.55 3487,2845.55 J4.1@3509.37,2845.55 ; v1(3262.21,1244.06) J3.19@3310.59,1244.06
  ART03 w10: v1(3262.21,1244.06) 3250.35,1232.19 2943,1232.19 2923,1252.19 2923,1974.03 2961,2012.03 2961,2122 2938,2145 2938,2397 2960.37,2419.37 3334.68,2419.37 3362,2446.69 3362,2594.69 3379.68,2612.37 3545.63,2612.37 3567,2633.74 3567,2747.74 3567,2774.37 3547,2794.37 3483,2794.37 3473,2804.37 3473,2835.55 3483,2845.55 J4.1@3509.37,2845.55
  BOTTOM w10: R27.2@2034.68,2689.37 2047.68,2702.37 2132,2702.37 v1(2145,2689.37)
MIC1_INP: J3.18 J4.2 R23.2 | length 4343.6
  TOP w10: v1(2145,2729.37) 2157.2,2717.17 2607,2717.17 2627,2737.17 2627,2819 2650.75,2842.74 3307.5,2842.74 3355.87,2794.37 3451,2794.37 3461,2804.37 3461,2835.55 3451,2845.55 J4.2@3430.63,2845.55 ; v1(3262.21,1204.68) 3266.15,1208.62 J3.18@3310.59,1208.62
  ART03 w10: v1(3262.21,1204.68) 3250.71,1216.19 2934.81,1216.19 2907,1244 2907,1980.7 2945,2018.7 2945,2115.37 2922,2138.37 2922,2403.63 2953.74,2435.37 3328.05,2435.37 3346,2453.32 3346,2601.32 3373.05,2628.37 3539,2628.37 3551,2640.37 3551,2767.37 3540,2778.37 3475,2778.37 3456,2797.37 3456,2820.18 J4.2@3430.63,2845.55
  BOTTOM w10: R23.2@2034.68,2729.37 2045.68,2718.37 2134,2718.37 v1(2145,2729.37)
MIPI_BL_PWM: J18.13 R184.2 | length 538.1
  BOTTOM w6.8: J18.13@2369.21,255.91 2369.21,321.4 2382.81,335 2480.1,335 2519.1,374 2768.68,374 R184.2@2805,410.32
MIPI_CSI_RX0_CLK0N: J3.132 J24.10 | length 2972.8
  TOP w4.5: J3.132@1416.89,1244.06 1454.32,1244.06 1467.29,1257.02 1489.62,1257.02 v1(1502.41,1244.23)
  ART03 w4: v1(99,363.73) 113.19,377.91 167.71,377.91 320.4,530.6 320.4,1111.88 352.2,1143.68 352.2,1207.64 363.05,1218.49 439.71,1218.49 450.84,1229.62 450.84,1269.31 455.53,1274 462.16,1274 466.84,1269.31 466.84,1229.62 477.97,1218.49 559.52,1218.49 570.65,1229.62 570.65,1269.11 575.74,1274.2 582.37,1274.2 587.05,1269.51 587.05,1229.22 597.78,1218.49 613.52,1218.49 625.05,1230.02 625.05,1269.51 629.74,1274.2 636.37,1274.2 641.05,1269.51 641.05,1229.22 651.78,1218.49 667.52,1218.49 679.05,1230.02 679.05,1269.51 683.74,1274.2 690.37,1274.2 695.05,1269.51 695.05,1229.22 705.78,1218.49 726.69,1218.49 886.6,1378.4 1364.8,1378.4 1379.44,1363.76 1379.44,1266.71 1389.89,1256.27 1490.37,1256.27 v1(1502.41,1244.23)
  BOTTOM w4.5: v1(99,363.73) 113.27,378 138.44,378 150.5,390.06 150.5,407.06 156.32,412.89 221.3,412.89 226.39,407.8 J24.10@257.91,407.8
MIPI_CSI_RX0_CLK0P: J3.131 J24.9 | length 2973.4
  TOP w4.5: J3.131@1416.89,1279.49 1454.32,1279.49 1467.29,1266.52 1489.62,1266.52 v1(1502.41,1279.31)
  ART03 w4: v1(99,403.1) 113.19,388.91 163.16,388.91 309.4,535.16 309.4,1116.43 341.2,1148.23 341.2,1212.2 358.49,1229.49 435.16,1229.49 439.84,1234.18 439.84,1273.87 450.97,1285 466.71,1285 477.84,1273.87 477.84,1234.18 482.53,1229.49 554.97,1229.49 559.65,1234.18 559.65,1273.67 571.18,1285.2 586.92,1285.2 598.05,1274.07 598.05,1233.78 602.34,1229.49 608.97,1229.49 614.05,1234.58 614.05,1274.07 625.18,1285.2 640.92,1285.2 652.05,1274.07 652.05,1233.78 656.34,1229.49 662.97,1229.49 668.05,1234.58 668.05,1274.07 679.18,1285.2 694.92,1285.2 706.05,1274.07 706.05,1233.78 710.34,1229.49 722.13,1229.49 882.04,1389.4 1369.36,1389.4 1390.44,1368.31 1390.44,1271.27 1394.44,1267.27 1490.37,1267.27 v1(1502.41,1279.31)
  BOTTOM w4.5: v1(99,403.1) 114.6,387.5 134.5,387.5 141,394 141,411 152.39,422.39 221.3,422.39 226.39,427.48 J24.9@257.91,427.48
MIPI_CSI_RX0_CLK1N: J3.124 J28.10 | length 2965.1
  TOP w4.5: J3.124@1416.89,1527.52 1454.32,1527.52 1467.29,1540.49 1489.62,1540.49 v1(1502.41,1527.69)
  ART03 w4: v1(70.06,956.68) 84.24,970.87 128.42,970.87 144.6,987.04 144.6,1425.6 221,1502 606,1502 618,1514 797.9,1514 809.03,1525.13 809.03,1539.71 813.71,1544.4 820.34,1544.4 825.03,1539.71 825.03,1514.13 836.16,1503 851.9,1503 863.03,1514.13 863.03,1539.71 867.71,1544.4 874.34,1544.4 879.03,1539.71 879.03,1514.13 890.16,1503 905.9,1503 917.03,1514.13 917.03,1539.71 921.71,1544.4 928.34,1544.4 933.03,1539.71 933.03,1514.13 944.16,1503 959.9,1503 971.03,1514.13 971.03,1539.71 975.71,1544.4 982.34,1544.4 987.03,1539.71 987.03,1514.13 998.16,1503 1013.9,1503 1025.03,1514.13 1025.03,1539.71 1029.71,1544.4 1036.34,1544.4 1041.03,1539.71 1041.03,1514.13 1052.16,1503 1072.27,1503 1083.4,1514.13 1083.4,1539.31 1088.09,1544 1094.71,1544 1099.4,1539.31 1099.4,1514.13 1110.53,1503 1126.27,1503 1137.4,1514.13 1137.4,1539.31 1142.09,1544 1148.71,1544 1153.4,1539.31 1153.4,1514.13 1164.53,1503 1184.64,1503 1195.77,1514.13 1195.77,1540.31 1200.46,1545 1207.09,1545 1211.77,1540.31 1211.77,1514.13 1222.9,1503 1270.53,1503 1274.53,1499 1274.53,1477.93 1285.26,1467.2 1301,1467.2 1312.53,1478.73 1312.53,1496.51 1318.22,1502.2 1324.53,1502.2 1328.53,1498.2 1328.53,1477.93 1339.26,1467.2 1355,1467.2 1366.13,1478.33 1366.13,1498.31 1370.82,1503 1461.56,1503 1472,1513.44 1472,1533.44 1478.29,1539.74 1490.37,1539.74 v1(1502.41,1527.69)
  BOTTOM w4.5: v1(70.06,956.68) 83.87,970.5 132.94,970.5 147.5,985.06 147.5,1088.68 156.5,1097.68 221.3,1097.68 226.39,1092.59 J28.10@257.91,1092.59
MIPI_CSI_RX0_CLK1P: J3.123 J28.9 | length 2966
  TOP w4.5: J3.123@1416.89,1562.95 1454.32,1562.95 1467.29,1549.99 1489.62,1549.99 v1(1502.41,1562.78)
  ART03 w4: v1(70.06,996.05) 84.24,981.87 123.87,981.87 133.6,991.6 133.6,1430.16 216.44,1513 601.44,1513 613.44,1525 793.34,1525 798.03,1529.69 798.03,1544.27 809.16,1555.4 824.9,1555.4 836.03,1544.27 836.03,1518.69 840.71,1514 847.34,1514 852.03,1518.69 852.03,1544.27 863.16,1555.4 878.9,1555.4 890.03,1544.27 890.03,1518.69 894.71,1514 901.34,1514 906.03,1518.69 906.03,1544.27 917.16,1555.4 932.9,1555.4 944.03,1544.27 944.03,1518.69 948.71,1514 955.34,1514 960.03,1518.69 960.03,1544.27 971.16,1555.4 986.9,1555.4 998.03,1544.27 998.03,1518.69 1002.71,1514 1009.34,1514 1014.03,1518.69 1014.03,1544.27 1025.16,1555.4 1040.9,1555.4 1052.03,1544.27 1052.03,1518.69 1056.71,1514 1067.71,1514 1072.4,1518.69 1072.4,1543.87 1083.53,1555 1099.27,1555 1110.4,1543.87 1110.4,1518.69 1115.09,1514 1121.71,1514 1126.4,1518.69 1126.4,1543.87 1137.53,1555 1153.27,1555 1164.4,1543.87 1164.4,1518.69 1169.09,1514 1180.09,1514 1184.77,1518.69 1184.77,1544.87 1195.9,1556 1211.64,1556 1222.77,1544.87 1222.77,1518.69 1227.46,1514 1275.09,1514 1285.53,1503.56 1285.53,1482.49 1289.82,1478.2 1296.44,1478.2 1301.53,1483.29 1301.53,1501.07 1313.66,1513.2 1329.09,1513.2 1339.53,1502.76 1339.53,1482.49 1343.82,1478.2 1350.44,1478.2 1355.13,1482.89 1355.13,1502.87 1366.26,1514 1457,1514 1461,1518 1461,1538 1473.73,1550.74 1490.37,1550.74 v1(1502.41,1562.78)
  BOTTOM w4.5: v1(70.06,996.05) 86.11,980 129,980 138,989 138,1092.62 152.56,1107.18 221.3,1107.18 226.39,1112.28 J28.9@257.91,1112.28
MIPI_CSI_RX0_D0N: J3.129 J24.12 | length 2955.5
  TOP w4.5: J3.129@1416.89,1350.35 1454.32,1350.35 1467.29,1363.32 1489.62,1363.32 v1(1502.41,1350.53)
  ART03 w4: v1(99,284.99) 113.19,299.17 130.77,299.17 348,516.4 348,1092 385,1129 385,1179 396.89,1190.89 742.65,1190.89 882.76,1331 988.44,1331 999.44,1320 1067,1320 1096,1349 1324.2,1349 1345.2,1328 1345.2,1222.8 1358.6,1209.4 1522.4,1209.4 1537.6,1224.6 1537.6,1304.4 1521.6,1320.4 1461.2,1320.4 1457.2,1324.4 1457.2,1353.84 1465.93,1362.57 1490.37,1362.57 v1(1502.41,1350.53)
  BOTTOM w4.5: v1(99,284.99) 114.01,300 163.94,300 178.5,314.56 178.5,364.5 187.52,373.52 221.3,373.52 226.39,368.43 J24.12@257.91,368.43
MIPI_CSI_RX0_D0P: J3.128 J24.11 | length 2955.5
  TOP w4.5: J3.128@1416.89,1385.79 1454.32,1385.79 1467.29,1372.82 1489.62,1372.82 v1(1502.41,1385.61)
  ART03 w4: v1(99,324.36) 113.19,310.17 126.22,310.17 337,520.96 337,1096.56 374,1133.56 374,1183.56 392.33,1201.89 738.09,1201.89 878.2,1342 993,1342 1004,1331 1062.44,1331 1091.44,1360 1328.76,1360 1356.2,1332.56 1356.2,1227.36 1363.16,1220.4 1517.84,1220.4 1526.6,1229.16 1526.6,1299.84 1517.04,1309.4 1456.64,1309.4 1446.2,1319.84 1446.2,1358.4 1461.37,1373.57 1490.37,1373.57 v1(1502.41,1385.61)
  BOTTOM w4.5: v1(99,324.36) 113.86,309.5 160,309.5 169,318.5 169,368.44 183.58,383.02 221.3,383.02 226.39,388.11 J24.11@257.91,388.11
MIPI_CSI_RX0_D1N: J3.127 J24.8 | length 2830.5
  TOP w4.5: J3.127@1416.89,1421.22 1454.32,1421.22 1467.29,1434.19 1542.21,1434.19 v1(1555,1421.39)
  ART03 w4: v1(99,442.47) 111.04,454.51 188.31,454.51 222.6,488.8 222.6,669.2 231.35,677.96 266.75,677.96 279,690.2 279,708.31 267.47,719.84 230.29,719.84 225.6,724.53 225.6,731.16 230.29,735.84 268.27,735.84 279,746.57 279,762.31 267.47,773.84 230.29,773.84 225.6,778.53 225.6,785.16 230.29,789.84 268.27,789.84 279,800.57 279,1117.4 319,1157.4 319,1321.8 328,1330.8 556.64,1330.8 573.44,1314 783.17,1314 875.17,1406 1458.8,1406 1486.24,1433.44 1542.96,1433.44 v1(1555,1421.39)
  BOTTOM w4.5: v1(99,442.47) 111.79,455.26 218.3,455.26 226.39,447.17 J24.8@257.91,447.17
MIPI_CSI_RX0_D1P: J3.126 J24.7 | length 2831.8
  TOP w4.5: J3.126@1416.89,1456.65 1454.32,1456.65 1467.29,1443.69 1542.21,1443.69 v1(1555,1456.48)
  ART03 w4: v1(99,477.55) 99,471 104.49,465.51 183.75,465.51 211.6,493.36 211.6,673.76 226.8,688.96 262.2,688.96 268,694.76 268,703.76 262.91,708.84 225.73,708.84 214.6,719.97 214.6,735.71 225.73,746.84 263.71,746.84 268,751.13 268,757.76 262.91,762.84 225.73,762.84 214.6,773.97 214.6,789.71 225.73,800.84 263.71,800.84 268,805.13 268,1121.96 308,1161.96 308,1326.36 323.44,1341.8 561.2,1341.8 578,1325 778.61,1325 870.61,1417 1454.24,1417 1481.68,1444.44 1542.96,1444.44 v1(1555,1456.48)
  BOTTOM w4.5: v1(99,477.55) 111.79,464.76 224.3,464.76 226.39,466.85 J24.7@257.91,466.85
MIPI_CSI_RX0_D2N: J3.121 J28.12 | length 2807.9
  TOP w4.5: J3.121@1416.89,1633.82 1454.32,1633.82 1467.29,1646.79 1497.21,1646.79 1502.41,1641.59 v1(1502.41,1633.99)
  ART03 w4: v1(109.42,877.94) 109.42,888.12 105.42,892.13 86.73,892.13 79.8,885.2 79.8,862.56 88.36,854 148,854 167,873 167,1135.6 197,1165.6 197,1283.4 184,1296.4 184,1328.07 ccw(c178.9,1328.07) 178.9,1333.17 cw(c178.9,1338.27) 173.8,1338.27 173.8,1344.07 cw(c178.9,1344.07) 178.9,1349.17 ccw(c178.9,1354.27) 184,1354.27 184,1360.07 ccw(c178.9,1360.07) 178.9,1365.17 cw(c178.9,1370.27) 173.8,1370.27 173.8,1376.07 cw(c178.9,1376.07) 178.9,1381.17 ccw(c178.9,1386.27) 184,1386.27 184,1392.07 ccw(c178.9,1392.07) 178.9,1397.17 cw(c178.9,1402.27) 173.8,1402.27 173.8,1408.07 cw(c178.9,1408.07) 178.9,1413.17 ccw(c178.9,1418.27) 184,1418.27 184,1437.56 231.44,1485 700,1485 706,1479 748,1479 754,1485 1223,1485 1258.4,1449.6 1437.6,1449.6 1477,1489 1531,1489 1542,1500 1542,1540 ccw(c1538,1540) 1538,1544 cw(c1538,1548) 1534,1548 1534,1556 cw(c1538,1556) 1538,1560 ccw(c1538,1564) 1542,1564 1542,1572 ccw(c1538,1572) 1538,1576 cw(c1538,1580) 1534,1580 1534,1588 cw(c1538,1588) 1538,1592 ccw(c1538,1596) 1542,1596 1542,1604 ccw(c1538,1604) 1538,1608 cw(c1538,1612) 1534,1612 1534,1620 cw(c1538,1620) 1538,1624 ccw(c1538,1628) 1542,1628 1542,1638 1531.96,1648.04 1509.04,1648.04 1502.41,1641.41 v1(1502.41,1633.99)
  BOTTOM w4.5: v1(109.42,877.94) 124.48,893 147,893 182.2,928.2 182.2,1033.4 207.11,1058.31 221.3,1058.31 226.39,1053.22 J28.12@257.91,1053.22
MIPI_CSI_RX0_D2P: J3.120 J28.11 | length 2802
  TOP w4.5: J3.120@1416.89,1669.25 1454.32,1669.25 1467.29,1656.29 1489.62,1656.29 v1(1502.41,1669.08)
  ART03 w4: v1(109.42,917.31) 95.24,903.13 82.17,903.13 68.8,889.76 68.8,858 83.8,843 152.56,843 178,868.44 178,1131.04 208,1161.04 208,1287.96 195,1300.96 195,1433 236,1474 695.44,1474 701.44,1468 752.56,1468 758.56,1474 1218.44,1474 1253.84,1438.6 1442.16,1438.6 1481.56,1478 1535.56,1478 1553,1495.44 1553,1642.56 1536.52,1659.04 1512.46,1659.04 v1(1502.41,1669.08)
  BOTTOM w4.5: v1(109.42,917.31) 124.24,902.5 143.06,902.5 172.7,932.14 172.7,1037.34 203.18,1067.81 221.3,1067.81 226.39,1072.91 J28.11@257.91,1072.91
MIPI_CSI_RX0_D3N: J3.119 J28.8 | length 2993
  TOP w4.5: J3.119@1416.89,1704.68 1454.32,1704.68 1467.29,1717.65 1542.21,1717.65 v1(1555,1704.86)
  ART03 w4: v1(70.06,1035.42) 84.24,1049.61 103.16,1049.61 117,1063.44 117,1440.44 209.56,1533 589.56,1533 619.56,1563 784.56,1563 793.56,1572 1157.37,1572 1168.7,1583.33 1168.7,1597.51 1173.38,1602.2 1180.01,1602.2 1184.7,1597.51 1184.7,1583.44 1195.14,1573 1212.25,1573 1222.7,1583.44 1222.7,1597.51 1227.38,1602.2 1238.8,1602.2 1244.06,1596.94 1244.06,1542.13 1255.19,1531 1270.93,1531 1282.06,1542.13 1282.06,1600.31 1286.74,1605 1293.37,1605 1298.06,1600.31 1298.06,1542.13 1309.19,1531 1324.93,1531 1336.06,1542.13 1336.06,1600.31 1340.74,1605 1347.37,1605 1352.06,1600.31 1352.06,1542.13 1363.19,1531 1429.56,1531 1453,1554.44 1453,1575.34 1441.87,1586.47 1399.69,1586.47 1395,1591.15 1395,1597.78 1399.69,1602.47 1441.87,1602.47 1453,1613.6 1453,1704 1465,1716 1543.86,1716 v1(1555,1704.86)
  BOTTOM w4.5: v1(70.06,1035.42) 85.63,1051 100.44,1051 114.5,1065.06 114.5,1126.06 125.49,1137.05 221.3,1137.05 226.39,1131.96 J28.8@257.91,1131.96
MIPI_CSI_RX0_D3P: J3.118 J28.7 | length 2993.2
  TOP w4.5: J3.118@1416.89,1740.12 1454.32,1740.12 1467.29,1727.15 1542.21,1727.15 v1(1555,1739.94)
  ART03 w4: v1(70.06,1074.79) 84.24,1060.61 98.61,1060.61 106,1068 106,1445 205,1544 585,1544 615,1574 780,1574 789,1583 1152.81,1583 1157.7,1587.88 1157.7,1602.07 1168.83,1613.2 1184.57,1613.2 1195.7,1602.07 1195.7,1588 1199.7,1584 1207.7,1584 1211.7,1588 1211.7,1602.07 1222.83,1613.2 1243.36,1613.2 1255.06,1601.5 1255.06,1546.69 1259.74,1542 1266.37,1542 1271.06,1546.69 1271.06,1604.87 1282.19,1616 1297.93,1616 1309.06,1604.87 1309.06,1546.69 1313.74,1542 1320.37,1542 1325.06,1546.69 1325.06,1604.87 1336.19,1616 1351.93,1616 1363.06,1604.87 1363.06,1546.69 1367.74,1542 1425,1542 1442,1559 1442,1570.78 1437.31,1575.47 1395.13,1575.47 1384,1586.6 1384,1602.34 1395.13,1613.47 1437.31,1613.47 1442,1618.15 1442,1708.56 1460.44,1727 1542.06,1727 v1(1555,1739.94)
  BOTTOM w4.5: v1(70.06,1074.79) 84.35,1060.5 96.5,1060.5 105,1069 105,1130 121.55,1146.55 221.3,1146.55 226.39,1151.65 J28.7@257.91,1151.65
MIPI_CSI_RX1_CLK0N: J3.116 J29.10 | length 2468.8
  TOP w4.5: J3.116@1416.89,1810.98 1454.32,1810.98 1467.29,1823.95 1489.62,1823.95 v1(1502.41,1811.16)
  ART03 w4: v1(70.06,1967.31) 84.24,1981.5 95.5,1981.5 102,1975 102,1945.4 64,1907.4 64,1891.64 cw(c58.8,1891.64) 58.8,1886.44 ccw(c58.8,1881.24) 53.6,1881.24 53.6,1875.64 ccw(c58.8,1875.64) 58.8,1870.44 cw(c58.8,1865.24) 64,1865.24 64,1859.64 cw(c58.8,1859.64) 58.8,1854.44 ccw(c58.8,1849.24) 53.6,1849.24 53.6,1843.64 ccw(c58.8,1843.64) 58.8,1838.44 cw(c58.8,1833.24) 64,1833.24 64,1659.44 78.44,1645 182.2,1645 194,1633.2 1354.76,1633.2 1391,1669.44 1391,1806.44 1407.76,1823.2 1490.37,1823.2 v1(1502.41,1811.16)
  BOTTOM w4.5: v1(70.06,1967.31) 74.31,1967.31 78.81,1962.81 78.81,1796.76 93.08,1782.48 221.3,1782.48 226.39,1777.39 J29.10@257.91,1777.39
MIPI_CSI_RX1_CLK0P: J3.115 J29.9 | length 2470.1
  TOP w4.5: J3.115@1416.89,1846.42 1454.32,1846.42 1467.29,1833.45 1489.62,1833.45 v1(1502.41,1846.24)
  ART03 w4: v1(70.06,2006.68) 84.24,1992.5 100.06,1992.5 113,1979.56 113,1940.84 75,1902.84 75,1664 83,1656 186.76,1656 198.56,1644.2 1350.2,1644.2 1380,1674 1380,1811 1403.2,1834.2 1490.37,1834.2 v1(1502.41,1846.24)
  BOTTOM w4.5: v1(70.06,2006.68) 70.06,1993.12 88.31,1974.87 88.31,1800.7 97.02,1791.98 221.3,1791.98 226.39,1797.07 J29.9@257.91,1797.07
MIPI_CSI_RX1_CLK1N: J3.108 J30.10 | length 2542.2
  TOP w4.5: J3.108@1416.89,2094.45 1454.32,2094.45 1467.29,2107.41 1543.21,2107.41 v1(1556,2094.62)
  ART03 w4: v1(70.06,2314.16) 84.24,2328.35 102.56,2328.35 113.69,2339.47 113.69,2367.71 118.37,2372.4 125,2372.4 129.69,2367.71 129.69,2339.47 140.82,2328.35 156.56,2328.35 167.69,2339.47 167.69,2367.71 172.37,2372.4 179,2372.4 183.69,2367.71 183.69,2339.47 194.82,2328.35 210.56,2328.35 221.69,2339.47 221.69,2367.71 226.37,2372.4 233,2372.4 237.69,2367.71 237.69,2339.47 248.82,2328.35 332.45,2328.35 341.6,2319.2 341.6,2032 356.6,2017 1318.36,2017 1332,2030.64 1332,2087.04 1350.62,2105.66 1544.96,2105.66 v1(1556,2094.62)
  BOTTOM w4.5: v1(70.06,2314.16) 85.39,2329.5 102.94,2329.5 117.5,2344.06 117.5,2459.06 124.71,2466.28 221.3,2466.28 226.39,2461.18 J30.10@257.91,2461.18
MIPI_CSI_RX1_CLK1P: J3.107 J30.9 | length 2542.7
  TOP w4.5: J3.107@1416.89,2129.88 1454.32,2129.88 1467.29,2116.91 1543.21,2116.91 v1(1556,2129.71)
  ART03 w4: v1(70.06,2353.53) 84.24,2339.35 98,2339.35 102.69,2344.03 102.69,2372.27 113.82,2383.4 129.56,2383.4 140.69,2372.27 140.69,2344.03 145.37,2339.35 152,2339.35 156.69,2344.03 156.69,2372.27 167.82,2383.4 183.56,2383.4 194.69,2372.27 194.69,2344.03 199.37,2339.35 206,2339.35 210.69,2344.03 210.69,2372.27 221.82,2383.4 237.56,2383.4 248.69,2372.27 248.69,2344.03 253.37,2339.35 337.01,2339.35 352.6,2323.76 352.6,2036.56 361.16,2028 1313.8,2028 1321,2035.2 1321,2091.6 1346.06,2116.66 1542.96,2116.66 v1(1556,2129.71)
  BOTTOM w4.5: v1(70.06,2353.53) 84.59,2339 99,2339 108,2348 108,2463 120.78,2475.78 221.3,2475.78 226.39,2480.87 J30.9@257.91,2480.87
MIPI_CSI_RX1_D0N: J3.113 J29.12 | length 2605.8
  TOP w4.5: J3.113@1416.89,1917.28 1454.32,1917.28 1467.29,1930.25 1521.75,1930.25 1527.41,1924.59 v1(1527.41,1917.46)
  ART03 w4: v1(171.82,1678.96) 161.63,1678.96 157.63,1682.96 157.63,1707.63 164,1714 189.8,1714 197.8,1706 197.8,1671.24 208.24,1660.8 231.67,1660.8 242.11,1671.24 242.11,1702.44 246.47,1706.8 257.6,1706.8 261.6,1702.8 261.6,1671.7 272.04,1661.26 1178.76,1661.26 1193.2,1675.7 1193.2,1687.74 cw(c1198.8,1687.74) 1198.8,1693.34 ccw(c1198.8,1698.94) 1204.4,1698.94 1204.4,1703.74 ccw(c1198.8,1703.74) 1198.8,1709.34 cw(c1198.8,1714.94) 1193.2,1714.94 1193.2,1725.09 1197.89,1729.78 1218.31,1729.78 1229.44,1740.91 1229.44,1756.65 1218.31,1767.78 1197.89,1767.78 1193.2,1772.46 1193.2,1787.07 1197.89,1791.75 1257.68,1791.75 1268.81,1802.88 1268.81,1818.62 1257.68,1829.75 1197.89,1829.75 1193.2,1834.44 1193.2,1841.07 1197.89,1845.75 1257.68,1845.75 1268.81,1856.88 1268.81,1872.62 1257.68,1883.75 1197.89,1883.75 1193.2,1888.44 1193.2,1900.4 1202.93,1910.13 1305,1910.13 1313,1902.13 1313,1816.24 1327.64,1801.6 1348.76,1801.6 1363.2,1816.04 1363.2,1905.64 1367.69,1910.13 1445.63,1910.13 1465,1929.5 1522.5,1929.5 1527.41,1924.59 v1(1527.41,1917.46)
  BOTTOM w4.5: v1(171.82,1678.96) 161.5,1678.96 157,1683.46 157,1734 166.11,1743.11 221.3,1743.11 226.39,1738.02 J29.12@257.91,1738.02
MIPI_CSI_RX1_D0P: J3.112 J29.11 | length 2606.8
  TOP w4.5: J3.112@1416.89,1952.72 1454.32,1952.72 1467.29,1939.75 1514.62,1939.75 v1(1527.41,1952.54)
  ART03 w4: v1(132.45,1678.96) 146.63,1693.15 146.63,1712.19 159.44,1725 194.36,1725 208.8,1710.56 208.8,1675.8 212.8,1671.8 227.11,1671.8 231.11,1675.8 231.11,1707 241.91,1717.8 262.16,1717.8 272.6,1707.36 272.6,1676.26 276.6,1672.26 1174.2,1672.26 1182.2,1680.26 1182.2,1729.65 1193.33,1740.78 1213.75,1740.78 1218.44,1745.46 1218.44,1752.09 1213.75,1756.78 1193.33,1756.78 1182.2,1767.91 1182.2,1791.62 1193.33,1802.75 1253.12,1802.75 1257.81,1807.44 1257.81,1814.07 1253.12,1818.75 1193.33,1818.75 1182.2,1829.88 1182.2,1845.62 1193.33,1856.75 1253.12,1856.75 1257.81,1861.44 1257.81,1868.07 1253.12,1872.75 1193.33,1872.75 1182.2,1883.88 1182.2,1904.96 1198.37,1921.13 1309.56,1921.13 1324,1906.69 1324,1820.8 1332.2,1812.6 1344.2,1812.6 1352.2,1820.6 1352.2,1910.2 1363.13,1921.13 1441.07,1921.13 1460.44,1940.5 1515.37,1940.5 v1(1527.41,1952.54)
  BOTTOM w4.5: v1(132.45,1678.96) 147.5,1694.02 147.5,1737.94 162.17,1752.61 221.3,1752.61 226.39,1757.7 J29.11@257.91,1757.7
MIPI_CSI_RX1_D1N: J3.111 J29.8 | length 2506.1
  TOP w4.5: J3.111@1416.89,1988.15 1454.32,1988.15 1467.29,2001.12 1542.21,2001.12 v1(1555,1988.33)
  ART03 w4: v1(132.45,1875.81) 146,1862.26 146,1754.44 156.64,1743.8 176.19,1743.8 188.72,1756.33 188.72,1791.52 193.41,1796.21 199.72,1796.21 203.72,1792.21 203.72,1754.53 214.45,1743.8 230.19,1743.8 241.72,1755.33 241.72,1785.52 246.41,1790.21 253.03,1790.21 257.32,1785.92 257.32,1754.93 268.25,1744 285.24,1744 291.4,1737.84 291.4,1704.6 307,1689 611,1689 634,1712 735.44,1712 758.44,1689 1144,1689 1163.8,1708.8 1163.8,1781.93 1152.67,1793.06 1123.69,1793.06 1119,1797.74 1119,1804.37 1123.69,1809.06 1152.67,1809.06 1163.8,1820.18 1163.8,1835.93 1152.67,1847.06 1123.69,1847.06 1119,1851.74 1119,1858.37 1123.69,1863.06 1152.67,1863.06 1163.8,1874.18 1163.8,1935 1171.4,1942.6 1418.16,1942.6 1431,1955.44 1431,1992.44 1438.92,2000.37 1542.96,2000.37 v1(1555,1988.33)
  BOTTOM w4.5: v1(132.45,1875.81) 147,1861.26 147,1835.56 160.71,1821.85 221.3,1821.85 226.39,1816.76 J29.8@257.91,1816.76
MIPI_CSI_RX1_D1P: J3.110 J29.7 | length 2505.8
  TOP w4.5: J3.110@1416.89,2023.58 1454.32,2023.58 1467.29,2010.62 1542.21,2010.62 v1(1555,2023.41)
  ART03 w4: v1(171.82,1875.81) 157,1861 157,1759 161.2,1754.8 171.63,1754.8 177.72,1760.89 177.72,1796.08 188.85,1807.21 204.28,1807.21 214.72,1796.77 214.72,1759.09 219,1754.8 225.63,1754.8 230.72,1759.89 230.72,1790.08 241.85,1801.21 257.59,1801.21 268.32,1790.48 268.32,1759.49 272.81,1755 289.8,1755 302.4,1742.4 302.4,1709.16 311.56,1700 606.44,1700 629.44,1723 740,1723 763,1700 1139.44,1700 1152.8,1713.36 1152.8,1777.37 1148.11,1782.06 1119.13,1782.06 1108,1793.18 1108,1808.93 1119.13,1820.06 1148.11,1820.06 1152.8,1824.74 1152.8,1831.37 1148.11,1836.06 1119.13,1836.06 1108,1847.18 1108,1862.93 1119.13,1874.06 1148.11,1874.06 1152.8,1878.74 1152.8,1939.56 1166.84,1953.6 1303.31,1953.6 ccw(c1303.31,1958.4) 1308.11,1958.4 cw(c1312.91,1958.4) 1312.91,1963.2 1319.31,1963.2 cw(c1319.31,1958.4) 1324.11,1958.4 ccw(c1328.91,1958.4) 1328.91,1953.6 1335.31,1953.6 ccw(c1335.31,1958.4) 1340.11,1958.4 cw(c1344.91,1958.4) 1344.91,1963.2 1351.31,1963.2 cw(c1351.31,1958.4) 1356.11,1958.4 ccw(c1360.91,1958.4) 1360.91,1953.6 1367.31,1953.6 ccw(c1367.31,1958.4) 1372.11,1958.4 cw(c1376.91,1958.4) 1376.91,1963.2 1383.31,1963.2 cw(c1383.31,1958.4) 1388.11,1958.4 ccw(c1392.91,1958.4) 1392.91,1953.6 1413.6,1953.6 1420,1960 1420,1997 1434.37,2011.37 1542.96,2011.37 v1(1555,2023.41)
  BOTTOM w4.5: v1(171.82,1875.81) 156.5,1860.5 156.5,1839.5 164.65,1831.35 221.3,1831.35 226.39,1836.44 J29.7@257.91,1836.44
MIPI_CSI_RX1_D2N: J3.105 J30.12 | length 2684.3
  TOP w4.5: J3.105@1416.89,2200.75 1454.32,2200.75 1467.29,2213.71 1503.85,2213.71 1516.5,2201.06 1516.5,2171.06 1529.06,2158.5 1638.5,2158.5 1646,2151 1646,2123 1638,2115 1620.71,2115 v1(1606,2129.71)
  ART03 w4: v1(70.06,2235.42) 82.24,2247.61 291.59,2247.61 307.4,2231.8 307.4,2009.04 327.44,1989 1337.16,1989 1361,2012.84 1361,2043 1372,2054 1639.56,2054 1652,2066.44 1652,2102.89 1637.22,2117.66 1618.04,2117.66 v1(1606,2129.71)
  BOTTOM w4.5: v1(70.06,2235.42) 84.13,2249.5 138.94,2249.5 154,2264.56 154,2421.06 159.84,2426.91 221.3,2426.91 226.39,2421.81 J30.12@257.91,2421.81
MIPI_CSI_RX1_D2P: J3.104 J30.11 | length 2680.1
  TOP w4.5: J3.104@1416.89,2236.18 1454.32,2236.18 1467.29,2223.21 1507.79,2223.21 1526,2205 1526,2175 1533,2168 1642.44,2168 1655.5,2154.94 1655.5,2119.06 1641.94,2105.5 1616.88,2105.5 v1(1606,2094.62)
  ART03 w4: v1(70.06,2274.79) 86.24,2258.61 296.15,2258.61 318.4,2236.36 318.4,2013.6 332,2000 1332.6,2000 1350,2017.4 1350,2047.56 1367.44,2065 1635,2065 1641,2071 1641,2098.33 1632.66,2106.66 1618.04,2106.66 v1(1606,2094.62)
  BOTTOM w4.5: v1(70.06,2274.79) 85.85,2259 135,2259 144.5,2268.5 144.5,2425 155.91,2436.41 221.3,2436.41 226.39,2441.5 J30.11@257.91,2441.5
